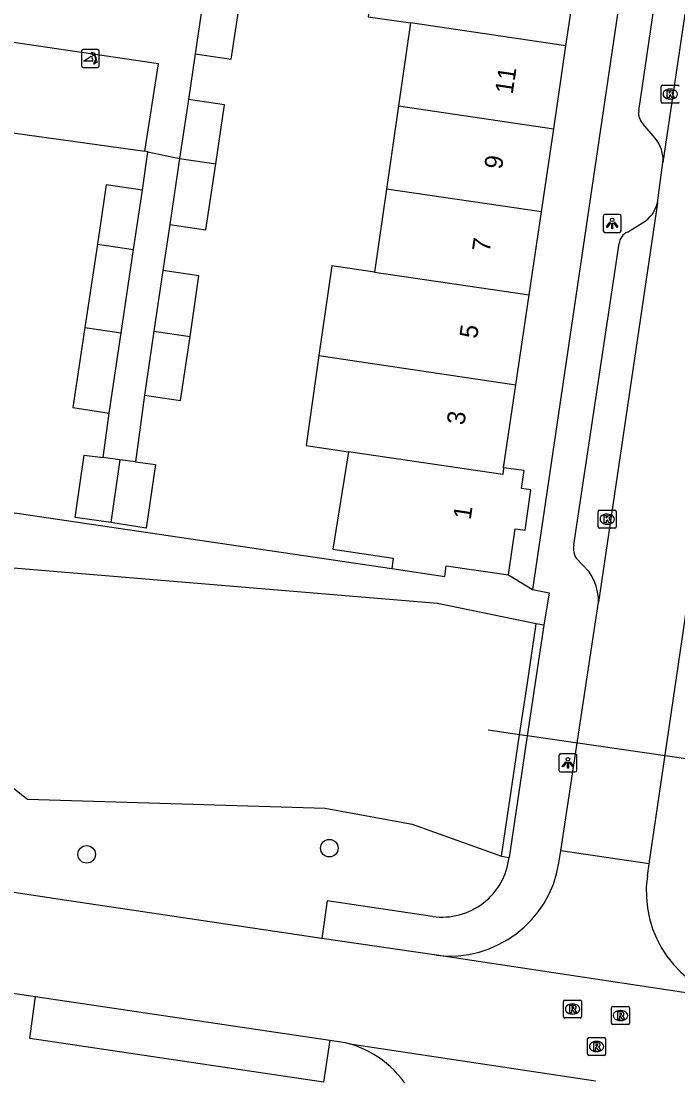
# Model space of a CAD drawing. Extents: x 164150 to 165261, y 382513 to 383432.
# Drawn here: x 164232.4 to 164268.9, y 382881.7 to 382940.4 of the extents above; entities that cross this region are included whole.
import ezdxf

# ---------------------------------------------------------------- set-up
doc = ezdxf.new("R2010")
doc.units = 0
for name, color, linetype in [('IMGEO_Boom', 7, 'Continuous'), ('IMGEO_Duiker', 7, 'Continuous'), ('IMGEO_Greppel_droge_sloot', 7, 'Continuous'), ('IMGEO_Groenvoorziening', 7, 'Continuous'), ('IMGEO_Kolk', 7, 'Continuous'), ('IMGEO_Lichtpunt', 7, 'Continuous'), ('IMGEO_Muur', 7, 'Continuous'), ('IMGEO_Pand', 7, 'Continuous'), ('IMGEO_Pand_nummerreeks', 7, 'Continuous'), ('IMGEO_Parkeervlak_open', 7, 'Continuous'), ('IMGEO_Poller', 7, 'Continuous'), ('IMGEO_Rijbaan_lokaal_gesloten', 7, 'Continuous'), ('IMGEO_Rijbaan_lokaal_open', 7, 'Continuous'), ('IMGEO_Rioolput', 7, 'Continuous'), ('IMGEO_Voetpad_open', 7, 'Continuous')]:
    doc.layers.add(name, color=color, linetype=linetype)

msp = doc.modelspace()

# ---------------------------------------------------------------- linework, layer by layer
at = {"layer": 'IMGEO_Boom'}
for centre in [(164249.518, 382894.393), (164236.011, 382894.048)]:
    msp.add_circle(centre, 0.489, dxfattribs=at)
at = {"layer": 'IMGEO_Duiker'}
msp.add_lwpolyline([(164273.212, 382898.819), (164271.474, 382899.069), (164271.046, 382899.131), (164260.536, 382900.643), (164260.114, 382900.704), (164258.36, 382900.956)], dxfattribs=at)
at = {"layer": 'IMGEO_Greppel_droge_sloot'}
msp.add_lwpolyline([(164261.037, 382906.886), (164255.544, 382908.013), (164223.229, 382910.702), (164224.108, 382905.852), (164226.912, 382901.661), (164232.717, 382897.121), (164249.289, 382896.62), (164254.14, 382895.739), (164259.105, 382893.945)], dxfattribs=at)
at = {"layer": 'IMGEO_Groenvoorziening'}
for points in [[(164221.548, 382914.606), (164252.997, 382909.963)], [(164259.493, 382909.604), (164260.833, 382908.792)]]:
    msp.add_lwpolyline(points, dxfattribs=at)
at = {"layer": 'IMGEO_Kolk'}
for p, q in [((164268.074, 382936.874), (164268.926, 382936.874)), ((164267.999, 382935.948), (164267.999, 382936.8)), ((164268.487, 382936.654), (164268.512, 382936.654)), ((164268.926, 382935.874), (164268.074, 382935.874)), ((164268.51, 382936.094), (164268.485, 382936.094)), ((164264.491, 382912.284), (164264.491, 382913.136)), ((164264.566, 382913.21), (164265.418, 382913.21)), ((164264.979, 382912.99), (164265.004, 382912.99)), ((164265.492, 382913.136), (164265.492, 382912.284)), ((164265.418, 382912.21), (164264.566, 382912.21)), ((164265.002, 382912.43), (164264.977, 382912.43))]:
    msp.add_line(p, q, dxfattribs=at)
for points in [[(164268.074, 382936.874), (164268.926, 382936.874)], [(164267.999, 382935.948), (164267.999, 382936.8)], [(164268.32, 382936.574), (164268.443, 382936.574), (164268.443, 382936.423), (164268.573, 382936.574), (164268.737, 382936.574), (164268.591, 382936.423), (164268.744, 382936.174), (164268.592, 382936.174), (164268.507, 382936.338), (164268.443, 382936.271), (164268.443, 382936.174), (164268.32, 382936.174), (164268.32, 382936.574)], [(164268.926, 382935.874), (164268.074, 382935.874)], [(164264.491, 382912.284), (164264.491, 382913.136)], [(164264.566, 382913.21), (164265.418, 382913.21)], [(164264.812, 382912.91), (164264.935, 382912.91), (164264.935, 382912.759), (164265.065, 382912.91), (164265.229, 382912.91), (164265.083, 382912.759), (164265.236, 382912.51), (164265.084, 382912.51), (164264.999, 382912.674), (164264.935, 382912.607), (164264.935, 382912.51), (164264.812, 382912.51), (164264.812, 382912.91)], [(164265.492, 382913.136), (164265.492, 382912.284)], [(164265.418, 382912.21), (164264.566, 382912.21)]]:
    msp.add_lwpolyline(points, dxfattribs=at)
for centre, start, end in [((164268.076, 382936.798), 91.55205, 178.44795), ((164268.076, 382936.798), 91.55205, 178.44795), ((164268.924, 382936.798), 1.55205, 88.44795), ((164268.924, 382936.798), 1.55205, 88.44795), ((164268.076, 382935.95), 181.55205, 268.44795), ((164268.076, 382935.95), 181.55205, 268.44795), ((164268.924, 382935.95), 271.55205, 358.44795), ((164268.924, 382935.95), 271.55205, 358.44795), ((164264.568, 382913.134), 91.55205, 178.44795), ((164264.568, 382913.134), 91.55205, 178.44795), ((164265.416, 382913.134), 1.55205, 88.44795), ((164265.416, 382913.134), 1.55205, 88.44795), ((164264.568, 382912.286), 181.55205, 268.44795), ((164264.568, 382912.286), 181.55205, 268.44795), ((164265.416, 382912.286), 271.55205, 358.44795), ((164265.416, 382912.286), 271.55205, 358.44795)]:
    msp.add_arc(centre, 0.0765, start, end, dxfattribs=at)
for centre, major_axis, ratio, start_param, end_param in [((164268.486, 382936.374), (-0.387, 0.002), 0.722429, 4.712389, 7.853982), ((164268.511, 382936.374), (-0.39, 0.002), 0.717154, 1.570796, 4.712389), ((164264.978, 382912.71), (-0.387, 0.002), 0.722429, 4.712389, 7.853982), ((164265.003, 382912.71), (-0.39, 0.002), 0.717154, 1.570796, 4.712389)]:
    msp.add_ellipse(centre, major_axis=major_axis, ratio=ratio, start_param=start_param, end_param=end_param, dxfattribs=at)
at = {"layer": 'IMGEO_Lichtpunt'}
for p, q in [((164264.768, 382929.579), (164264.768, 382928.772)), ((164264.768, 382929.579), (164264.768, 382928.772)), ((164265.67, 382929.674), (164264.862, 382929.674)), ((164265.67, 382929.674), (164264.862, 382929.674)), ((164265.764, 382928.772), (164265.764, 382929.579)), ((164265.764, 382928.772), (164265.764, 382929.579)), ((164264.862, 382928.678), (164265.67, 382928.678)), ((164264.862, 382928.678), (164265.67, 382928.678)), ((164262.304, 382899.546), (164262.304, 382898.739)), ((164262.304, 382899.546), (164262.304, 382898.739)), ((164263.206, 382899.641), (164262.398, 382899.641)), ((164263.206, 382899.641), (164262.398, 382899.641)), ((164263.3, 382898.739), (164263.3, 382899.546)), ((164263.3, 382898.739), (164263.3, 382899.546)), ((164262.398, 382898.645), (164263.206, 382898.645)), ((164262.398, 382898.645), (164263.206, 382898.645))]:
    msp.add_line(p, q, dxfattribs=at)
for points in [[(164265.142, 382929.243), (164265.181, 382929.215), (164264.993, 382928.953), (164264.955, 382928.98), (164265.142, 382929.243)], [(164265.354, 382929.215), (164265.392, 382929.242), (164265.579, 382928.98), (164265.54, 382928.952), (164265.354, 382929.215)], [(164265.244, 382929.195), (164265.291, 382929.195), (164265.291, 382928.873), (164265.244, 382928.873), (164265.244, 382929.195)], [(164262.678, 382899.21), (164262.717, 382899.182), (164262.529, 382898.92), (164262.491, 382898.947), (164262.678, 382899.21)], [(164262.78, 382899.162), (164262.827, 382899.162), (164262.827, 382898.84), (164262.78, 382898.84), (164262.78, 382899.162)], [(164262.89, 382899.182), (164262.928, 382899.209), (164263.115, 382898.947), (164263.076, 382898.919), (164262.89, 382899.182)]]:
    msp.add_lwpolyline(points, dxfattribs=at)
for centre in [(164265.267, 382929.377), (164262.803, 382899.344)]:
    msp.add_circle(centre, 0.0994, dxfattribs=at)
for centre, start, end in [((164264.862, 382929.579), 90, 180), ((164264.862, 382929.579), 90, 180), ((164265.67, 382929.579), 0, 90), ((164265.67, 382929.579), 0, 90), ((164264.862, 382928.772), 180, 270), ((164264.862, 382928.772), 180, 270), ((164265.67, 382928.772), 270, 0), ((164265.67, 382928.772), 270, 360), ((164262.398, 382899.546), 90, 180), ((164262.398, 382899.546), 90, 180), ((164263.206, 382899.546), 0, 90), ((164263.206, 382899.546), 0, 90), ((164262.398, 382898.739), 180, 270), ((164262.398, 382898.739), 180, 270), ((164263.206, 382898.739), 270, 0), ((164263.206, 382898.739), 270, 360)]:
    msp.add_arc(centre, 0.0946, start, end, dxfattribs=at)
at = {"layer": 'IMGEO_Muur'}
for points in [[(164221.548, 382914.606), (164252.997, 382909.963)], [(164259.105, 382893.945), (164259.851, 382898.941), (164260.114, 382900.704), (164260.528, 382903.478), (164261.037, 382906.886)], [(164261.454, 382906.808), (164260.536, 382900.643), (164259.528, 382893.877)], [(164261.454, 382906.808), (164261.037, 382906.886)], [(164259.105, 382893.945), (164259.528, 382893.877)]]:
    msp.add_lwpolyline(points, dxfattribs=at)
at = {"layer": 'IMGEO_Pand'}
for points in [[(164254.797, 382945.531), (164252.432, 382945.875), (164251.678, 382940.679), (164254.043, 382940.336)], [(164262.692, 382939.056), (164263.459, 382944.249)], [(164242.558, 382942.035), (164242.054, 382938.614)], [(164242.054, 382938.614), (164244.062, 382938.318), (164244.566, 382941.738)], [(164254.043, 382940.336), (164253.372, 382935.717)], [(164262.692, 382939.056), (164254.043, 382940.336)], [(164262.011, 382934.439), (164262.692, 382939.056)], [(164241.676, 382936.074), (164241.184, 382932.794)], [(164243.192, 382932.497), (164243.684, 382935.773), (164241.676, 382936.074)], [(164253.372, 382935.717), (164252.7, 382931.09)], [(164253.372, 382935.717), (164262.011, 382934.439)], [(164261.328, 382929.813), (164262.011, 382934.439)], [(164241.184, 382932.794), (164240.632, 382929.115)], [(164241.184, 382932.794), (164243.192, 382932.497)], [(164240.632, 382929.115), (164242.639, 382928.814), (164243.192, 382932.497)], [(164239.12, 382931.022), (164237.101, 382931.326), (164236.605, 382928.03)], [(164238.625, 382927.731), (164239.12, 382931.022)], [(164252.7, 382931.09), (164252.029, 382926.471)], [(164261.328, 382929.813), (164252.7, 382931.09)], [(164260.646, 382925.196), (164261.328, 382929.813)], [(164236.605, 382928.03), (164235.905, 382923.387)], [(164236.605, 382928.03), (164238.625, 382927.731)], [(164237.925, 382923.088), (164238.625, 382927.731)], [(164240.253, 382926.552), (164239.755, 382923.176)], [(164241.764, 382922.879), (164242.262, 382926.256), (164240.253, 382926.552)], [(164252.029, 382926.471), (164249.664, 382926.815), (164248.943, 382921.816)], [(164252.029, 382926.471), (164260.646, 382925.196)], [(164259.908, 382920.194), (164260.646, 382925.196)], [(164235.905, 382923.387), (164235.233, 382918.923), (164237.252, 382918.618)], [(164235.905, 382923.387), (164237.925, 382923.088)], [(164237.252, 382918.618), (164237.925, 382923.088)], [(164239.755, 382923.176), (164239.231, 382919.621)], [(164239.231, 382919.621), (164241.239, 382919.324), (164241.764, 382922.879)], [(164239.755, 382923.176), (164241.764, 382922.879)], [(164248.943, 382921.816), (164248.22, 382916.805), (164250.585, 382916.462)], [(164248.943, 382921.816), (164259.908, 382920.194)], [(164259.224, 382915.563), (164259.908, 382920.194)], [(164250.585, 382916.462), (164249.707, 382911.041), (164253.082, 382910.538), (164252.997, 382909.963)], [(164259.224, 382915.563), (164259.17, 382915.191), (164250.585, 382916.462)], [(164237.353, 382912.531), (164235.371, 382912.798), (164235.877, 382916.278), (164236.919, 382916.138)], [(164237.859, 382916.012), (164236.919, 382916.138)], [(164237.859, 382916.012), (164237.353, 382912.531)], [(164238.731, 382915.895), (164239.841, 382915.746), (164239.328, 382912.213), (164237.353, 382912.531)], [(164238.731, 382915.895), (164237.859, 382916.012)], [(164259.493, 382909.604), (164259.873, 382912.167), (164260.416, 382912.106), (164260.741, 382914.348), (164260.219, 382914.424), (164260.358, 382915.427), (164259.224, 382915.563)], [(164252.997, 382909.963), (164255.943, 382909.525), (164256.031, 382910.119), (164259.493, 382909.604)]]:
    msp.add_lwpolyline(points, dxfattribs=at)
at = {"layer": 'IMGEO_Parkeervlak_open'}
msp.add_lwpolyline([(164228.007, 382934.761), (164239.252, 382933.191)], dxfattribs=at)
at = {"layer": 'IMGEO_Poller'}
for p, q in [((164235.716, 382938.761), (164235.716, 382937.954)), ((164235.716, 382938.761), (164235.716, 382937.954)), ((164236.618, 382938.856), (164235.81, 382938.856)), ((164236.618, 382938.856), (164235.81, 382938.856)), ((164236.712, 382937.954), (164236.712, 382938.761)), ((164236.712, 382937.954), (164236.712, 382938.761)), ((164235.81, 382937.859), (164236.618, 382937.859)), ((164235.81, 382937.859), (164236.618, 382937.859))]:
    msp.add_line(p, q, dxfattribs=at)
for points in [[(164236.395, 382938.585), (164236.383, 382938.512), (164236.258, 382938.717)], [(164236.258, 382938.717), (164236.489, 382938.651), (164236.418, 382938.619)], [(164236.351, 382938.212), (164235.838, 382938.212), (164236.268, 382938.487)], [(164236.411, 382938.04), (164236.477, 382938.271), (164236.507, 382938.203)], [(164236.543, 382938.176), (164236.615, 382938.165), (164236.411, 382938.04)]]:
    msp.add_lwpolyline(points, dxfattribs=at)
for centre, radius, start, end in [((164235.81, 382938.761), 0.0946, 90, 180), ((164235.81, 382938.761), 0.0946, 90, 180), ((164236.037, 382938.272), 0.516, 349.35686, 42.29123), ((164236.618, 382938.761), 0.0946, 0, 90), ((164236.618, 382938.761), 0.0946, 0, 90), ((164236.023, 382938.262), 0.332, 351.32473, 42.4854), ((164236.037, 382938.272), 0.476, 351.75274, 41.16905), ((164235.81, 382937.954), 0.0946, 180, 270), ((164235.81, 382937.954), 0.0946, 180, 270), ((164236.618, 382937.954), 0.0946, 270, 0), ((164236.618, 382937.954), 0.0946, 270, 0)]:
    msp.add_arc(centre, radius, start, end, dxfattribs=at)
at = {"layer": 'IMGEO_Rijbaan_lokaal_gesloten'}
for points in [[(164249.104, 382889.368), (164234.778, 382891.507), (164227.654, 382892.577)], [(164255.48, 382888.431), (164249.104, 382889.368)], [(164272.211, 382885.919), (164255.48, 382888.431)], [(164230.5, 382886.525), (164233.168, 382886.129)], [(164233.168, 382886.129), (164233.894, 382886.021), (164249.553, 382883.698)], [(164249.553, 382883.698), (164250.393, 382883.573), (164250.665, 382883.499)]]:
    msp.add_lwpolyline(points, dxfattribs=at)
at = {"layer": 'IMGEO_Rijbaan_lokaal_open'}
for points in [[(164275.91, 382985.375), (164268.094, 382932.574)], [(164239.252, 382933.191), (164240.014, 382938.066), (164225.239, 382940.236), (164224.485, 382935.291)], [(164242.054, 382938.614), (164241.676, 382936.074)], [(164239.418, 382933.157), (164239.252, 382933.191)], [(164239.418, 382933.157), (164241.184, 382932.794)], [(164267.789, 382930.331), (164268.094, 382932.574)], [(164267.789, 382930.331), (164264.507, 382908.099)], [(164267.326, 382893.52), (164269.536, 382908.558), (164269.642, 382909.28)], [(164262.402, 382894.251), (164264.507, 382908.099)], [(164262.301, 382893.575), (164262.402, 382894.251)], [(164267.326, 382893.52), (164262.402, 382894.251)], [(164267.227, 382892.855), (164267.326, 382893.52)], [(164250.665, 382883.499), (164264.329, 382881.444)]]:
    msp.add_lwpolyline(points, dxfattribs=at)
for centre, radius, start, end in [((164256.212, 382894.554), 6.167, 263.18116, 350.86177), ((164273.301, 382891.961), 6.139, 171.6262, 259.77356), ((164249.012, 382877.942), 5.797, 27.58534, 73.43057)]:
    msp.add_arc(centre, radius, start, end, dxfattribs=at)
at = {"layer": 'IMGEO_Rioolput'}
for p, q in [((164262.56, 382885.014), (164262.56, 382885.866)), ((164262.635, 382885.94), (164263.487, 382885.94)), ((164263.561, 382885.866), (164263.561, 382885.014)), ((164263.048, 382885.72), (164263.073, 382885.72)), ((164265.229, 382884.651), (164265.229, 382885.503)), ((164265.304, 382885.577), (164266.156, 382885.577)), ((164265.717, 382885.357), (164265.742, 382885.357)), ((164266.23, 382885.503), (164266.23, 382884.651)), ((164263.487, 382884.94), (164262.635, 382884.94)), ((164263.071, 382885.16), (164263.046, 382885.16)), ((164265.74, 382884.797), (164265.715, 382884.797)), ((164266.156, 382884.577), (164265.304, 382884.577)), ((164263.899, 382882.927), (164263.899, 382883.779)), ((164263.974, 382883.853), (164264.826, 382883.853)), ((164264.387, 382883.633), (164264.412, 382883.633)), ((164264.9, 382883.779), (164264.9, 382882.927)), ((164264.826, 382882.853), (164263.974, 382882.853)), ((164264.41, 382883.073), (164264.385, 382883.073))]:
    msp.add_line(p, q, dxfattribs=at)
for points in [[(164262.56, 382885.014), (164262.56, 382885.866)], [(164262.635, 382885.94), (164263.487, 382885.94)], [(164263.561, 382885.866), (164263.561, 382885.014)], [(164263.149, 382885.638), (164262.897, 382885.64), (164262.897, 382885.24)], [(164262.897, 382885.24), (164263.021, 382885.24), (164263.021, 382885.402), (164263.032, 382885.402)], [(164263.075, 382885.559), (164263.021, 382885.559), (164263.021, 382885.478)], [(164263.021, 382885.478), (164263.073, 382885.478)], [(164263.079, 382885.373), (164263.15, 382885.24), (164263.29, 382885.24), (164263.225, 382885.366)], [(164265.229, 382884.651), (164265.229, 382885.503)], [(164265.304, 382885.577), (164266.156, 382885.577)], [(164265.818, 382885.275), (164265.566, 382885.277), (164265.566, 382884.877)], [(164265.744, 382885.196), (164265.69, 382885.196), (164265.69, 382885.115)], [(164266.23, 382885.503), (164266.23, 382884.651)], [(164263.487, 382884.94), (164262.635, 382884.94)], [(164265.566, 382884.877), (164265.69, 382884.877), (164265.69, 382885.039), (164265.701, 382885.039)], [(164265.69, 382885.115), (164265.742, 382885.115)], [(164265.748, 382885.01), (164265.819, 382884.877), (164265.959, 382884.877), (164265.894, 382885.003)], [(164266.156, 382884.577), (164265.304, 382884.577)], [(164263.899, 382882.927), (164263.899, 382883.779)], [(164263.974, 382883.853), (164264.826, 382883.853)], [(164264.488, 382883.551), (164264.236, 382883.553), (164264.236, 382883.153)], [(164264.414, 382883.472), (164264.36, 382883.472), (164264.36, 382883.391)], [(164264.9, 382883.779), (164264.9, 382882.927)], [(164264.826, 382882.853), (164263.974, 382882.853)], [(164264.236, 382883.153), (164264.36, 382883.153), (164264.36, 382883.315), (164264.371, 382883.315)], [(164264.36, 382883.391), (164264.412, 382883.391)], [(164264.418, 382883.286), (164264.489, 382883.153), (164264.629, 382883.153), (164264.564, 382883.279)]]:
    msp.add_lwpolyline(points, dxfattribs=at)
for centre, radius, start, end in [((164262.637, 382885.864), 0.0765, 91.55205, 178.44795), ((164262.637, 382885.864), 0.0765, 91.55205, 178.44795), ((164263.485, 382885.864), 0.0765, 1.55205, 88.44795), ((164263.485, 382885.864), 0.0765, 1.55205, 88.44795), ((164263.031, 382885.349), 0.0533, 26.02933, 88.69889), ((164263.057, 382885.667), 0.19, 274.7715, 282.96867), ((164263.081, 382885.463), 0.0964, 77.00612, 93.18647), ((164263.095, 382885.52), 0.0378, 276.66336, 79.67722), ((164263.148, 382885.528), 0.109, 350.36119, 89.41601), ((164263.146, 382885.528), 0.112, 277.58423, 350.98172), ((164263.13, 382885.313), 0.108, 29.51342, 73.79051), ((164265.306, 382885.501), 0.0765, 91.55205, 178.44795), ((164265.306, 382885.501), 0.0765, 91.55205, 178.44795), ((164265.75, 382885.1), 0.0964, 77.00612, 93.18647), ((164265.764, 382885.157), 0.0378, 276.66336, 79.67722), ((164265.817, 382885.165), 0.109, 350.36119, 89.41601), ((164266.154, 382885.501), 0.0765, 1.55205, 88.44795), ((164266.154, 382885.501), 0.0765, 1.55205, 88.44795), ((164262.637, 382885.016), 0.0765, 181.55205, 268.44795), ((164262.637, 382885.016), 0.0765, 181.55205, 268.44795), ((164263.485, 382885.016), 0.0765, 271.55205, 358.44795), ((164263.485, 382885.016), 0.0765, 271.55205, 358.44795), ((164265.306, 382884.653), 0.0765, 181.55205, 268.44795), ((164265.306, 382884.653), 0.0765, 181.55205, 268.44795), ((164265.7, 382884.986), 0.0533, 26.02933, 88.69889), ((164265.726, 382885.304), 0.19, 274.7715, 282.96867), ((164265.815, 382885.165), 0.112, 277.58423, 350.98172), ((164265.799, 382884.95), 0.108, 29.51342, 73.79051), ((164266.154, 382884.653), 0.0765, 271.55205, 358.44795), ((164266.154, 382884.653), 0.0765, 271.55205, 358.44795), ((164263.976, 382883.777), 0.0765, 91.55205, 178.44795), ((164263.976, 382883.777), 0.0765, 91.55205, 178.44795), ((164264.42, 382883.376), 0.0964, 77.00612, 93.18647), ((164264.434, 382883.433), 0.0378, 276.66336, 79.67722), ((164264.487, 382883.441), 0.109, 350.36119, 89.41601), ((164264.485, 382883.441), 0.112, 277.58423, 350.98172), ((164264.824, 382883.777), 0.0765, 1.55205, 88.44795), ((164264.824, 382883.777), 0.0765, 1.55205, 88.44795), ((164263.976, 382882.929), 0.0765, 181.55205, 268.44795), ((164263.976, 382882.929), 0.0765, 181.55205, 268.44795), ((164264.37, 382883.262), 0.0533, 26.02933, 88.69889), ((164264.396, 382883.58), 0.19, 274.7715, 282.96867), ((164264.469, 382883.226), 0.108, 29.51342, 73.79051), ((164264.824, 382882.929), 0.0765, 271.55205, 358.44795), ((164264.824, 382882.929), 0.0765, 271.55205, 358.44795)]:
    msp.add_arc(centre, radius, start, end, dxfattribs=at)
for centre, major_axis, ratio, start_param, end_param in [((164263.047, 382885.44), (-0.387, 0.002), 0.722429, 4.712389, 7.853982), ((164263.072, 382885.44), (-0.39, 0.002), 0.717154, 1.570796, 4.712389), ((164265.716, 382885.077), (-0.387, 0.002), 0.722429, 4.712389, 7.853982), ((164265.741, 382885.077), (-0.39, 0.002), 0.717154, 1.570796, 4.712389), ((164264.386, 382883.353), (-0.387, 0.002), 0.722429, 4.712389, 7.853982), ((164264.411, 382883.353), (-0.39, 0.002), 0.717154, 1.570796, 4.712389)]:
    msp.add_ellipse(centre, major_axis=major_axis, ratio=ratio, start_param=start_param, end_param=end_param, dxfattribs=at)
at = {"layer": 'IMGEO_Voetpad_open'}
for points in [[(164272.503, 382987.831), (164260.833, 382908.792)], [(164266.749, 382935.45), (164273.731, 382982.918)], [(164267.655, 382933.922), (164266.998, 382934.711)], [(164239.12, 382931.022), (164239.418, 382933.157)], [(164240.632, 382929.115), (164240.253, 382926.552)], [(164266.124, 382928.691), (164266.95, 382929.201)], [(164263.126, 382911.278), (164265.647, 382928.053)], [(164239.231, 382919.621), (164238.731, 382915.895)], [(164236.919, 382916.138), (164237.252, 382918.618)], [(164263.986, 382909.785), (164263.282, 382910.518)], [(164260.833, 382908.792), (164261.755, 382908.618), (164261.454, 382906.808)], [(164255.27, 382890.598), (164249.392, 382891.466), (164249.104, 382889.368)], [(164249.553, 382883.698), (164249.19, 382881.363), (164232.835, 382883.801), (164233.168, 382886.129)]]:
    msp.add_lwpolyline(points, dxfattribs=at)
for centre, radius, start, end in [((164267.533, 382935.303), 0.797, 169.34882, 227.89282), ((164266.185, 382932.698), 1.913, 356.29502, 39.78249), ((164266.033, 382930.759), 1.808, 300.49597, 346.31789), ((164266.429, 382927.965), 0.787, 112.82072, 173.61211), ((164264.054, 382911.072), 0.95, 167.51242, 215.68677), ((164261.527, 382908.102), 2.98, 359.94834, 34.39557), ((164255.807, 382894.305), 3.746, 261.76282, 353.43547)]:
    msp.add_arc(centre, radius, start, end, dxfattribs=at)

# ---------------------------------------------------------------- texts
at = {"layer": 'IMGEO_Pand_nummerreeks'}
for s, rotation, p in [('11', 81.3748, (164259.721, 382936.335)), ('9', 81.6793, (164259.124, 382932.153)), ('7', 81.41647, (164258.445, 382927.545)), ('5', 81.71505, (164257.741, 382922.728)), ('3', 81.8049, (164257.035, 382917.914)), ('1', 81.31678, (164257.385, 382912.648))]:
    msp.add_text(s, height=1, rotation=rotation, dxfattribs=at).set_placement(p)

doc.saveas('drawing.dxf')
